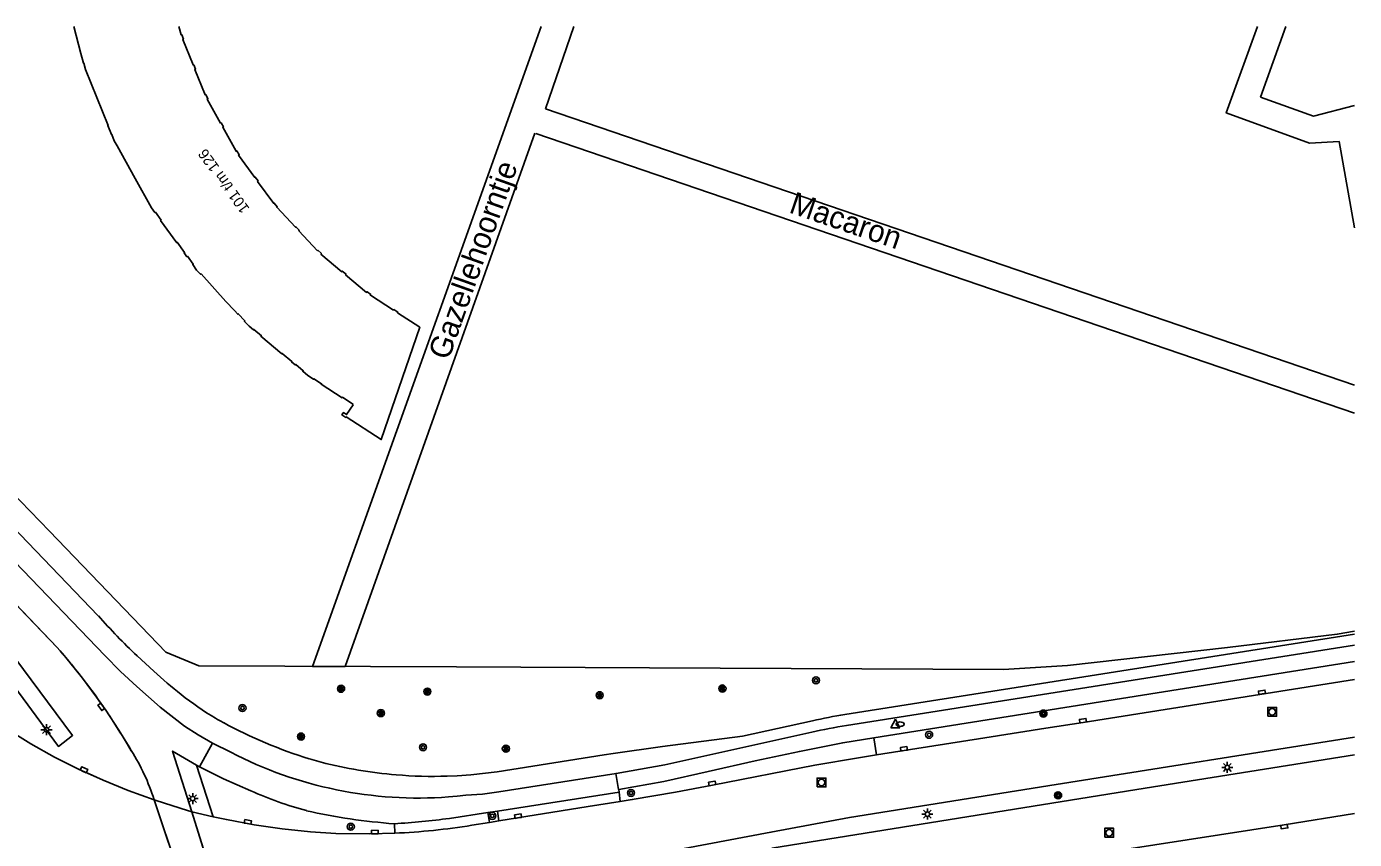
# Model space of a CAD drawing. Extents: x 132573 to 132944, y 398226 to 398676.
# Drawn here: x 132790.1 to 132940.1, y 398584.5 to 398676.3 of the extents above; entities that cross this region are included whole.
import ezdxf

# ---------------------------------------------------------------- set-up
doc = ezdxf.new("R2010")
doc.units = 0
for name, color, linetype in [('gg-afsc-hekwerk', 7, 'Continuous'), ('gg-anno-openbare ruimte label', 7, 'Continuous'), ('gg-knt-plantopografie kant verharding', 7, 'Continuous'), ('gg-knt-verharding', 7, 'Continuous'), ('gg-knt-verharding nz', 7, 'Continuous'), ('gt-anno-plantopografie huisnummer', 7, 'Continuous'), ('gt-bbg-plantopografie pand', 7, 'Continuous'), ('gt-grn-groengrens', 7, 'Continuous'), ('gt-symb-boom', 7, 'Continuous'), ('gt-symb-brandkraan', 7, 'Continuous'), ('gt-symb-kolk', 7, 'Continuous'), ('gt-symb-lichtmast', 7, 'Continuous'), ('gt-symb-portaalmast', 7, 'Continuous'), ('gt-symb-rioolschacht', 7, 'Continuous'), ('gt-symb-solitaire heester', 7, 'Continuous'), ('gt-symb-waterafsluiter', 7, 'Continuous'), ('ir-asfa-asfalt arcering', 7, 'Continuous'), ('ir-asfa-asfalt rood', 7, 'Continuous')]:
    doc.layers.add(name, color=color, linetype=linetype)

msp = doc.modelspace()

# ---------------------------------------------------------------- linework, layer by layer
at = {"layer": 'gg-afsc-hekwerk'}
for points in [[(132784.62, 398632.89), (132784.95, 398630.43), (132786.14, 398626.1), (132792.73, 398619.32), (132805.84, 398605.65)], [(132805.84, 398605.65), (132809.57, 398604.09), (132838.69, 398603.98), (132860.47, 398603.86), (132900.48, 398603.69), (132907.71, 398604.13), (132925.77, 398606.17), (132938.17, 398607.68), (132940.11, 398608.01)]]:
    msp.add_lwpolyline(points, dxfattribs=at)
at = {"layer": 'gg-knt-plantopografie kant verharding'}
for p, q in [((132851.93, 398676.34), (132848.73, 398667.05)), ((132932.38, 398676.34), (132929.49, 398668.38)), ((132848.73, 398667.05), (132940.11, 398635.81)), ((132847.64, 398664.24), (132940.11, 398632.64))]:
    msp.add_line(p, q, dxfattribs=at)
for points in [[(132847.52, 398664.29), (132826.1, 398604.01), (132822.42, 398604.04), (132841.46, 398657.38), (132844.51, 398665.9), (132848.24, 398676.34)], [(132940.11, 398653.6), (132938.39, 398663.34), (132935.02, 398663.18), (132925.64, 398666.59), (132929.18, 398676.34)], [(132929.49, 398668.38), (132935.48, 398666.21), (132940.11, 398667.42)]]:
    msp.add_lwpolyline(points, dxfattribs=at)
at = {"layer": 'gg-knt-verharding'}
for p, q in [((132782.02, 398626.63), (132798.23, 398609.76)), ((132793.58, 398606.18), (132777.82, 398622.6)), ((132882.56, 398598.61), (132940.11, 398607.67)), ((132882.75, 398597.36), (132940.11, 398606.43)), ((132885.82, 398595.98), (132940.11, 398604.61)), ((132906.42, 398590.68), (132940.11, 398596.04)), ((132809.64, 398592.68), (132811.11, 398595.37)), ((132813.19, 398594.33), (132811.11, 398595.37)), ((132811.19, 398587.04), (132809.32, 398592.87)), ((132809.32, 398592.87), (132809.64, 398592.68)), ((132822.07, 398593.58), (132823.4, 398593.22)), ((132857.05, 398589.84), (132857.02, 398590.13)), ((132857.18, 398588.77), (132857.05, 398589.84)), ((132804.52, 398588.97), (132804.75, 398588.89)), ((132804.75, 398588.89), (132808.29, 398587.74)), ((132857.18, 398588.77), (132853.55, 398588.19)), ((132808.78, 398587.62), (132808.29, 398587.74)), ((132808.78, 398587.62), (132811.19, 398587.04)), ((132843.3, 398587.67), (132842.24, 398587.51)), ((132842.24, 398587.51), (132842.42, 398586.4)), ((132843.48, 398586.57), (132843.3, 398587.67)), ((132853.55, 398588.19), (132843.48, 398586.57)), ((132831.67, 398586.26), (132831.71, 398585.19)), ((132842.42, 398586.4), (132840.42, 398586.08)), ((132843.48, 398586.57), (132842.42, 398586.4))]:
    msp.add_line(p, q, dxfattribs=at)
for points in [[(132779.5, 398625.49), (132798.95, 398605.27), (132800.72, 398603.47), (132802.58, 398601.75), (132805.21, 398599.45), (132807.98, 398597.3), (132809.52, 398596.29), (132811.11, 398595.37)], [(132804.52, 398588.97), (132801.61, 398590.02), (132798.78, 398591.17), (132796, 398592.43), (132793.27, 398593.8), (132790.61, 398595.29), (132788.01, 398596.9), (132785.48, 398598.6), (132782.99, 398600.36), (132781.58, 398601.43), (132780.22, 398602.55), (132776.26, 398606.05), (132773.65, 398608.51), (132771.33, 398610.93), (132769.16, 398613.44), (132767.11, 398616.04), (132765.18, 398618.74), (132764.27, 398620.12), (132763.11, 398622.09)], [(132802.6, 398605.23), (132803.54, 398604.36), (132804.5, 398603.51)], [(132905.27, 398597.05), (132909.48, 398597.71), (132940.11, 398602.56)], [(132856.39, 398594.2), (132861.94, 398595), (132870.99, 398596.14), (132878.89, 398597.88)], [(132856.72, 398591.95), (132862.21, 398592.9), (132878.82, 398596.61)], [(132857.02, 398590.13), (132862.1, 398591.05), (132867.1, 398592.16), (132872.44, 398593.35), (132877.42, 398594.44), (132882.32, 398595.41), (132885.82, 398595.98)], [(132905.27, 398597.05), (132898.37, 398595.97), (132886.13, 398594.03)], [(132808.78, 398587.62), (132806.61, 398594.46), (132809.32, 398592.87)], [(132840.3, 398591.79), (132843.29, 398592.14), (132855.38, 398594.06), (132856.39, 398594.2)], [(132886.13, 398594.03), (132884.1, 398593.71), (132879.18, 398592.86), (132867.6, 398590.62), (132863.42, 398589.83), (132858.53, 398588.98), (132857.18, 398588.77)], [(132874.31, 398583.51), (132916.49, 398590.28), (132940.11, 398594.05)], [(132809.64, 398592.68), (132812.36, 398591.35), (132815.46, 398589.98)], [(132837.64, 398591.64), (132838.75, 398591.68), (132840.3, 398591.79)], [(132856.72, 398591.95), (132843.48, 398589.86), (132841.62, 398589.6), (132839.75, 398589.47), (132838.78, 398589.37), (132837.8, 398589.29)], [(132857.02, 398590.13), (132856.98, 398590.13), (132856.69, 398591.95), (132856.72, 398591.95)], [(132906.42, 398590.68), (132883.09, 398586.98), (132874.21, 398585.3), (132864.41, 398583.45)], [(132831.71, 398585.19), (132828.91, 398585.11), (132825.05, 398585.15), (132822.18, 398585.35), (132819, 398585.69), (132815.84, 398586.15), (132812.7, 398586.72), (132811.19, 398587.04)], [(132875.33, 398577.14), (132913.92, 398583.32), (132932.16, 398586.13), (132940.11, 398587.42)]]:
    msp.add_lwpolyline(points, dxfattribs=at)
for centre, radius, start, end in [((132849.06, 398654.44), 67.67, 221.3116, 226.6407), ((132736.63, 398556.51), 75.57, 30.1932, 41.0964), ((132833.86, 398634.7), 42.84, 226.7246, 232.1525), ((132833.87, 398634.7), 42.85, 232.1527, 238.4769), ((132839, 398646.83), 55.9, 240.4973, 241.5552), ((132838.48, 398645.94), 54.87, 241.5828, 252.5904), ((132895.76, 398519.21), 79.23, 99.4525, 102.3477), ((132891.36, 398544.55), 54.77, 99.2501, 103.1592), ((132782.12, 398581.95), 23.48, 17.411, 32.3633), ((132834.38, 398635.16), 46, 242.5733, 274.2656), ((132835.82, 398641.12), 49.49, 255.4707, 265.4248), ((132836.06, 398640.4), 48.79, 265.0693, 271.8543), ((132832.37, 398627.45), 41.11, 245.7153, 254.9956), ((132836.51, 398652.88), 66.8, 257.2191, 265.8518), ((132828, 398664.23), 79.13, 272.6836, 279.0304)]:
    msp.add_arc(centre, radius, start, end, dxfattribs=at)
at = {"layer": 'gg-knt-verharding nz'}
for p, q in [((132857.05, 398589.84), (132843.3, 398587.67)), ((132807.78, 398579.29), (132804.52, 398588.97)), ((132808.78, 398587.62), (132811.67, 398578.43)), ((132842.24, 398587.51), (132837.88, 398586.86))]:
    msp.add_line(p, q, dxfattribs=at)
msp.add_arc((132826.88, 398668.01), 81.89, 273.3564, 277.7211, dxfattribs=at)
at = {"layer": 'gt-bbg-plantopografie pand'}
msp.add_lwpolyline([(132795.46, 398676.34), (132796.26, 398673.28), (132796.55, 398672.21), (132796.58, 398672.22), (132796.77, 398671.48), (132799.33, 398665.17), (132799.3, 398665.16), (132799.71, 398664.13), (132799.74, 398664.14), (132800.02, 398663.43), (132800.34, 398662.87), (132802.38, 398659.19), (132804.23, 398655.84), (132804.62, 398655.32), (132804.67, 398655.36), (132805.32, 398654.46), (132805.27, 398654.42), (132807.08, 398651.92), (132807.14, 398651.96), (132807.98, 398650.81), (132807.92, 398650.77), (132808.24, 398650.34), (132808.29, 398650.38), (132808.95, 398649.48), (132808.89, 398649.44), (132809.33, 398648.82), (132809.78, 398648.35), (132809.83, 398648.4), (132812.64, 398645.28), (132813.61, 398644.24), (132813.98, 398643.84), (132814.03, 398643.89), (132814.79, 398643.08), (132814.74, 398643.03), (132815.25, 398642.48), (132815.75, 398642.06), (132815.8, 398642.11), (132816.65, 398641.4), (132816.6, 398641.35), (132818.97, 398639.36), (132819.01, 398639.41), (132820.1, 398638.5), (132820.06, 398638.45), (132820.47, 398638.1), (132820.52, 398638.15), (132821.37, 398637.44), (132821.32, 398637.39), (132821.9, 398636.9), (132822.54, 398636.48), (132822.58, 398636.54), (132823.45, 398635.98), (132823.41, 398635.92), (132825.76, 398634.39), (132825.8, 398634.45), (132826.99, 398633.68), (132826.95, 398633.62), (132827, 398633.59), (132826.28, 398632.49), (132825.92, 398632.73), (132825.74, 398632.46), (132826.19, 398632.17), (132826.24, 398632.23), (132830.18, 398629.67), (132834.53, 398642.37), (132832.01, 398644), (132832.06, 398644.07), (132831.6, 398644.36), (132831.56, 398644.3), (132828.96, 398645.98), (132829.01, 398646.05), (132828.58, 398646.37), (132828.53, 398646.3), (132826.15, 398648.3), (132826.21, 398648.36), (132825.79, 398648.71), (132825.74, 398648.64), (132823.37, 398650.64), (132823.42, 398650.69), (132823.03, 398651.06), (132822.98, 398651.01), (132820.86, 398653.27), (132820.92, 398653.33), (132820.55, 398653.72), (132820.49, 398653.67), (132818.38, 398655.93), (132818.44, 398655.98), (132818.1, 398656.4), (132818.04, 398656.35), (132816.22, 398658.85), (132816.28, 398658.9), (132815.96, 398659.34), (132815.9, 398659.29), (132814.08, 398661.8), (132814.15, 398661.84), (132813.86, 398662.3), (132813.79, 398662.25), (132812.29, 398664.96), (132812.36, 398665), (132812.1, 398665.47), (132812.03, 398665.43), (132810.52, 398668.14), (132810.6, 398668.18), (132810.36, 398668.67), (132810.29, 398668.63), (132809.13, 398671.5), (132809.21, 398671.53), (132809, 398672.03), (132808.93, 398672), (132807.77, 398674.88), (132807.84, 398674.9), (132807.67, 398675.41), (132807.6, 398675.39), (132807.34, 398676.34)], dxfattribs=at)
at = {"layer": 'gt-grn-groengrens'}
msp.add_line((132885.82, 398595.98), (132886.13, 398594.03), dxfattribs=at)
msp.add_lwpolyline([(132787.2, 398603.83), (132787.25, 398603.83), (132788.8, 398605.01), (132795.33, 398596.23), (132793.72, 398595), (132787.2, 398603.83)], dxfattribs=at)
at = {"layer": 'gt-symb-boom'}
for centre, radius in [((132879.29, 398602.46), 0.4), ((132879.29, 398602.46), 0.2), ((132814.51, 398599.33), 0.4), ((132814.51, 398599.33), 0.2), ((132892.07, 398596.31), 0.4), ((132892.07, 398596.31), 0.2), ((132834.91, 398594.9), 0.4), ((132834.91, 398594.9), 0.2), ((132858.4, 398589.74), 0.4), ((132858.4, 398589.74), 0.2), ((132842.73, 398587.15), 0.4), ((132842.73, 398587.15), 0.2), ((132826.75, 398585.92), 0.4), ((132826.75, 398585.92), 0.2)]:
    msp.add_circle(centre, radius, dxfattribs=at)
at = {"layer": 'gt-symb-brandkraan'}
for centre, radius, start, end in [((132888.54, 398597.51), 0.206, 107.5669, 252.4331), ((132889.38, 398594.84), 3, 106.892, 107.5669), ((132888.78, 398596.82), 0.938, 73.108, 106.892), ((132888.18, 398594.84), 3, 72.4331, 73.108), ((132889.03, 398597.51), 0.206, 287.567, 72.4331), ((132889.38, 398600.17), 3, 252.4331, 253.108), ((132888.78, 398598.2), 0.938, 253.108, 286.8921), ((132888.18, 398600.17), 3, 286.8921, 287.567)]:
    msp.add_arc(centre, radius, start, end, dxfattribs=at)
at = {"layer": 'gt-symb-kolk'}
for points in [[(132929.69, 398600.92), (132930.06, 398600.97), (132930, 398601.37), (132929.26, 398601.25), (132929.32, 398600.86), (132929.69, 398600.92)], [(132798.72, 398599.58), (132798.51, 398599.89), (132798.18, 398599.66), (132798.61, 398599.04), (132798.94, 398599.27), (132798.72, 398599.58)], [(132909.48, 398597.71), (132909.85, 398597.77), (132909.78, 398598.16), (132909.04, 398598.04), (132909.11, 398597.65), (132909.48, 398597.71)], [(132889.25, 398594.53), (132889.62, 398594.58), (132889.56, 398594.98), (132888.82, 398594.86), (132888.88, 398594.47), (132889.25, 398594.53)], [(132796.52, 398592.18), (132796.86, 398592.02), (132797.03, 398592.39), (132796.35, 398592.7), (132796.18, 398592.34), (132796.52, 398592.18)], [(132867.6, 398590.62), (132867.97, 398590.69), (132867.89, 398591.08), (132867.16, 398590.94), (132867.23, 398590.55), (132867.6, 398590.62)], [(132845.67, 398586.92), (132846.04, 398586.98), (132845.98, 398587.37), (132845.24, 398587.26), (132845.3, 398586.86), (132845.67, 398586.92)], [(132815.08, 398586.27), (132815.45, 398586.21), (132815.52, 398586.6), (132814.78, 398586.73), (132814.71, 398586.34), (132815.08, 398586.27)], [(132829.47, 398585.12), (132829.84, 398585.13), (132829.83, 398585.53), (132829.08, 398585.51), (132829.09, 398585.11), (132829.47, 398585.12)], [(132932.16, 398586.13), (132931.79, 398586.07), (132931.85, 398585.68), (132932.59, 398585.79), (132932.53, 398586.19), (132932.16, 398586.13)]]:
    msp.add_lwpolyline(points, dxfattribs=at)
at = {"layer": 'gt-symb-lichtmast'}
for p, q in [((132792.38, 398597.13), (132792.38, 398597.51)), ((132792.13, 398596.88), (132791.75, 398596.88)), ((132792.2, 398597.06), (132791.93, 398597.33)), ((132792.2, 398596.71), (132791.93, 398596.44)), ((132792.38, 398596.63), (132792.38, 398596.26)), ((132792.55, 398597.06), (132792.82, 398597.33)), ((132792.82, 398596.44), (132792.55, 398596.71)), ((132792.63, 398596.88), (132793, 398596.88)), ((132925.57, 398592.8), (132925.31, 398593.07)), ((132925.75, 398592.87), (132925.75, 398593.25)), ((132925.92, 398592.8), (132926.19, 398593.07)), ((132925.5, 398592.62), (132925.12, 398592.62)), ((132925.57, 398592.45), (132925.31, 398592.18)), ((132925.75, 398592.37), (132925.75, 398592)), ((132926.19, 398592.18), (132925.92, 398592.45)), ((132926, 398592.62), (132926.37, 398592.62)), ((132808.64, 398589.1), (132808.27, 398589.1)), ((132808.72, 398589.27), (132808.45, 398589.54)), ((132808.72, 398588.92), (132808.45, 398588.66)), ((132808.89, 398589.35), (132808.89, 398589.72)), ((132808.89, 398588.85), (132808.89, 398588.47)), ((132809.07, 398589.27), (132809.33, 398589.54)), ((132809.33, 398588.66), (132809.07, 398588.92)), ((132809.14, 398589.1), (132809.52, 398589.1)), ((132891.62, 398587.34), (132891.25, 398587.34)), ((132891.7, 398587.52), (132891.43, 398587.78)), ((132891.7, 398587.16), (132891.43, 398586.9)), ((132891.88, 398587.59), (132891.88, 398587.97)), ((132891.88, 398587.09), (132891.88, 398586.72)), ((132892.05, 398587.52), (132892.32, 398587.78)), ((132892.32, 398586.9), (132892.05, 398587.16)), ((132892.12, 398587.34), (132892.5, 398587.34))]:
    msp.add_line(p, q, dxfattribs=at)
for centre in [(132792.38, 398596.88), (132925.75, 398592.62), (132808.89, 398589.1), (132891.88, 398587.34)]:
    msp.add_circle(centre, 0.25, dxfattribs=at)
at = {"layer": 'gt-symb-portaalmast'}
for centre, radius in [((132904.98, 398598.71), 0.4), ((132904.98, 398598.71), 0.33), ((132904.98, 398598.71), 0.27), ((132904.98, 398598.71), 0.21), ((132904.98, 398598.71), 0.15), ((132906.64, 398589.47), 0.4), ((132906.64, 398589.47), 0.33), ((132906.64, 398589.47), 0.27), ((132906.64, 398589.47), 0.21), ((132906.64, 398589.47), 0.15)]:
    msp.add_circle(centre, radius, dxfattribs=at)
at = {"layer": 'gt-symb-rioolschacht'}
for points in [[(132930.32, 398598.41), (132931.32, 398598.41), (132931.32, 398599.41), (132930.32, 398599.41)], [(132879.42, 398590.42), (132880.42, 398590.42), (132880.42, 398591.42), (132879.42, 398591.42)], [(132911.9, 398584.74), (132912.9, 398584.74), (132912.9, 398585.74), (132911.9, 398585.74)]]:
    msp.add_lwpolyline(points, close=True, dxfattribs=at)
for centre in [(132930.82, 398598.91), (132879.92, 398590.92), (132912.4, 398585.24)]:
    msp.add_circle(centre, 0.375, dxfattribs=at)
at = {"layer": 'gt-symb-solitaire heester'}
for centre in [(132825.65, 398601.51), (132868.73, 398601.54), (132835.4, 398601.19), (132854.86, 398600.78), (132830.14, 398598.76), (132821.13, 398596.11), (132844.26, 398594.74)]:
    msp.add_circle(centre, 0.4, dxfattribs=at)
for centre, start, end in [((132825.3, 398601.71), 270, 30), ((132826, 398601.71), 150, 270), ((132868.39, 398601.73), 270, 30), ((132869.08, 398601.73), 150, 270), ((132825.3, 398601.31), 330, 90), ((132825.65, 398601.91), 210, 330), ((132825.65, 398601.11), 30, 150), ((132826, 398601.31), 90, 210), ((132835.06, 398601.39), 270, 30), ((132835.06, 398600.99), 330, 90), ((132835.4, 398601.59), 210, 330), ((132835.4, 398600.79), 30, 150), ((132835.75, 398601.39), 150, 270), ((132835.75, 398600.99), 90, 210), ((132854.52, 398600.97), 270, 30), ((132854.52, 398600.57), 330, 90), ((132854.86, 398601.17), 210, 330), ((132854.86, 398600.37), 30, 150), ((132855.21, 398600.97), 150, 270), ((132855.21, 398600.57), 90, 210), ((132868.39, 398601.34), 330, 90), ((132868.73, 398601.94), 210, 330), ((132868.73, 398601.14), 30, 150), ((132869.08, 398601.34), 90, 210), ((132829.79, 398598.96), 270, 30), ((132829.79, 398598.56), 330, 90), ((132830.14, 398599.16), 210, 330), ((132830.49, 398598.96), 150, 270), ((132830.49, 398598.56), 90, 210), ((132830.14, 398598.36), 30, 150), ((132820.78, 398596.31), 270, 30), ((132820.78, 398595.91), 330, 90), ((132821.13, 398596.51), 210, 330), ((132821.13, 398595.71), 30, 150), ((132821.47, 398596.31), 150, 270), ((132821.47, 398595.91), 90, 210), ((132843.91, 398594.94), 270, 30), ((132843.91, 398594.54), 330, 90), ((132844.26, 398595.14), 210, 330), ((132844.26, 398594.34), 30, 150), ((132844.6, 398594.94), 150, 270), ((132844.6, 398594.54), 90, 210)]:
    msp.add_arc(centre, 0.4, start, end, dxfattribs=at)
at = {"layer": 'gt-symb-waterafsluiter'}
for p, q in [((132887.76, 398597.09), (132888.26, 398598.09)), ((132888.26, 398598.09), (132888.76, 398597.09)), ((132888.76, 398597.09), (132887.76, 398597.09))]:
    msp.add_line(p, q, dxfattribs=at)
at = {"layer": 'ir-asfa-asfalt arcering'}
msp.add_lwpolyline([(132788.01, 398596.9), (132790.61, 398595.29), (132793.27, 398593.8), (132796, 398592.43), (132796.18, 398592.34), (132796.18, 398592.34), (132796.86, 398592.02), (132796.87, 398592.03), (132798.78, 398591.17), (132801.61, 398590.02), (132804.52, 398588.97), (132807.78, 398579.29), (132803.46, 398580.58), (132797.7, 398582.47), (132798.99, 398579.06)], dxfattribs=at)
msp.add_lwpolyline([(132811.67, 398578.43), (132811.22, 398578.51), (132809.49, 398578.87), (132807.78, 398579.29), (132804.52, 398588.97), (132804.75, 398588.89), (132808.29, 398587.74), (132808.78, 398587.62)], close=True, dxfattribs=at)
at = {"layer": 'ir-asfa-asfalt rood'}
for points in [[(132779.5, 398625.49), (132798.95, 398605.27), (132800.72, 398603.47), (132802.58, 398601.75), (132805.21, 398599.45), (132807.98, 398597.3), (132809.52, 398596.29), (132811.11, 398595.37), (132809.64, 398592.68), (132809.32, 398592.87), (132806.61, 398594.46), (132808.52, 398588.44)], [(132793.58, 398606.18), (132788.07, 398611.92), (132788.08, 398611.93), (132787.56, 398612.48), (132787.55, 398612.46), (132777.82, 398622.6)], [(132798.94, 398599.27), (132798.94, 398599.27), (132798.51, 398599.89), (132798.51, 398599.88)], [(132808.56, 398588.31), (132808.78, 398587.62), (132808.29, 398587.74), (132804.75, 398588.89), (132804.52, 398588.97)]]:
    msp.add_lwpolyline(points, dxfattribs=at)
for centre, radius, start, end in [((132736.63, 398556.51), 75.57, 35.0304, 41.0964), ((132736.63, 398556.51), 75.57, 30.1932, 34.4618), ((132782.12, 398581.95), 23.48, 17.411, 32.3633), ((132808.77, 398588.45), 0.25, 181.9307, 213.3744)]:
    msp.add_arc(centre, radius, start, end, dxfattribs=at)

# ---------------------------------------------------------------- texts
at = {"layer": 'gg-anno-openbare ruimte label'}
for s, rotation, p in [('Gazellehoorntje', 70.4, (132837.79, 398638.54)), ('Macaron', 341.1, (132876.13, 398655.36))]:
    msp.add_text(s, height=2.5, rotation=rotation, dxfattribs=at).set_placement(p)
at = {"layer": 'gt-anno-plantopografie huisnummer'}
msp.add_text('101 t/m 126', height=1.2, rotation=126.0048, dxfattribs=at).set_placement((132815.36, 398655.79))

doc.saveas('drawing.dxf')
